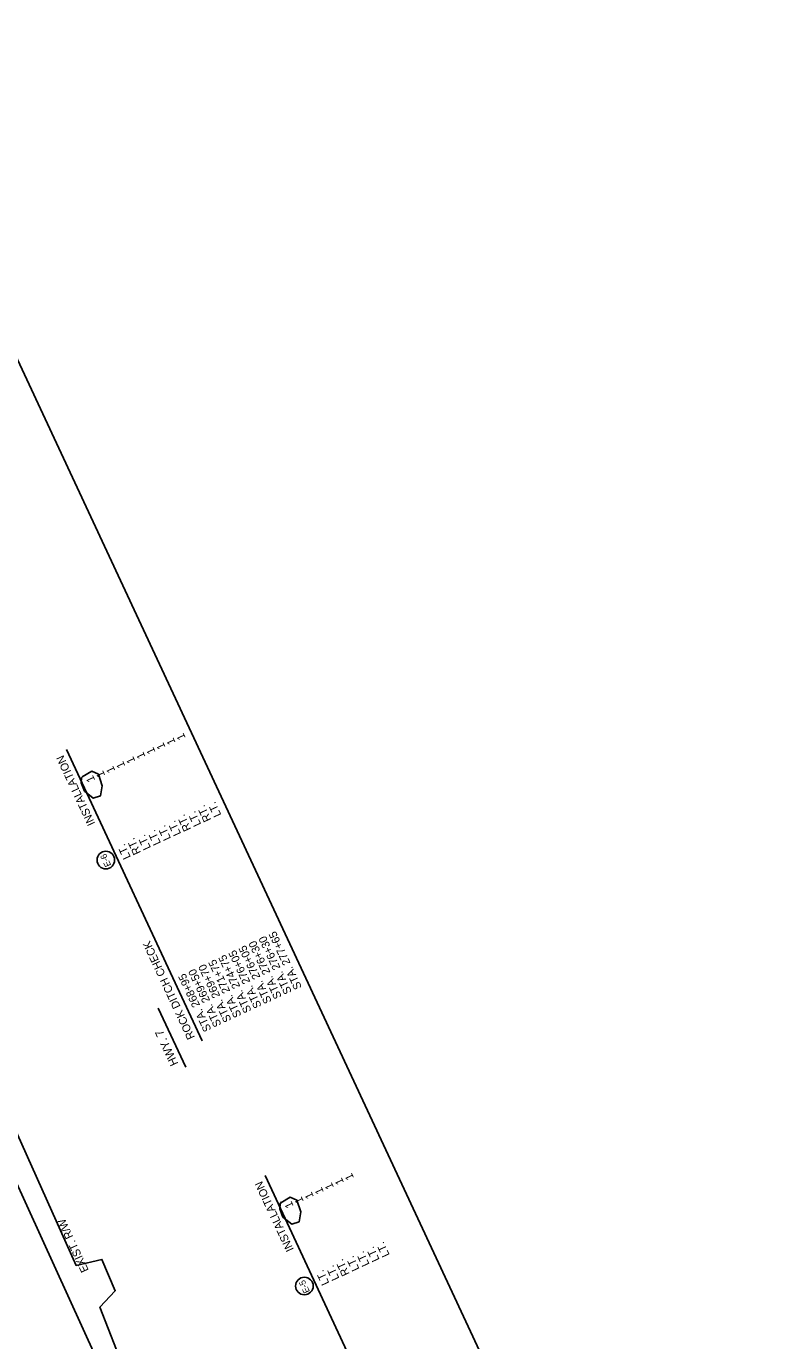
# Model space of a CAD drawing. Extents: x 964229 to 965790, y 1899262 to 1901149.
# Drawn here: x 965239 to 965790, y 1900163 to 1901149 of the extents above; entities that cross this region are included whole.
import ezdxf

# ---------------------------------------------------------------- set-up
doc = ezdxf.new("R2010")
doc.units = 0
for name, color, linetype in [('1', 7, 'Continuous'), ('44', 7, 'Continuous'), ('NO PLOT', 7, 'Continuous'), ('R_Draft', 7, 'Continuous'), ('S_TREE', 7, 'Continuous')]:
    doc.layers.add(name, color=color, linetype=linetype)

msp = doc.modelspace()

# ---------------------------------------------------------------- linework, layer by layer
at = {"layer": '1'}
for centre in [(965298.54, 1900523.47), (965447.48, 1900204.08)]:
    msp.add_circle(centre, 6.61, dxfattribs=at)
at = {"layer": '44'}
for p, q in [((965370.87, 1900387.83), (965269.02, 1900606.26)), ((965358.48, 1900368.05), (965337.83, 1900412.32)), ((965519.81, 1900068.44), (965417.95, 1900286.86))]:
    msp.add_line(p, q, dxfattribs=at)
at = {"layer": 'NO PLOT'}
msp.add_lwpolyline([(965789.77, 1899702.74), (965115.54, 1901148.63), (964643.21, 1900928.38), (964770.42, 1900655.58), (964831.6, 1900684.11), (965011.21, 1900298.93), (964950.03, 1900270.4), (965070.98, 1900011.03), (965126.95, 1900037.14), (965271.77, 1899726.58), (965215.79, 1899700.48), (965317.44, 1899482.49)], close=True, dxfattribs=at)
msp.add_lwpolyline([(965789.77, 1899702.74), (965115.54, 1901148.63), (964643.21, 1900928.38), (964770.42, 1900655.58), (964831.6, 1900684.11), (965011.21, 1900298.93), (964950.03, 1900270.4), (965070.98, 1900011.03), (965126.95, 1900037.14), (965271.77, 1899726.58), (965215.79, 1899700.48), (965317.44, 1899482.49)], close=True, dxfattribs=at)
msp.add_lwpolyline([(965789.77, 1899702.74), (965115.54, 1901148.63), (964643.21, 1900928.38), (964770.42, 1900655.58), (964831.6, 1900684.11), (965011.21, 1900298.93), (964950.03, 1900270.4), (965070.98, 1900011.03), (965126.95, 1900037.14), (965271.77, 1899726.58), (965215.79, 1899700.48), (965317.44, 1899482.49)], close=True, dxfattribs=at)
msp.add_lwpolyline([(965789.77, 1899702.74), (965115.54, 1901148.63), (964643.21, 1900928.38), (964770.42, 1900655.58), (964831.6, 1900684.11), (965011.21, 1900298.93), (964950.03, 1900270.4), (965070.98, 1900011.03), (965126.95, 1900037.14), (965271.77, 1899726.58), (965215.79, 1899700.48), (965317.44, 1899482.49)], close=True, dxfattribs=at)
for points in [[(965176.25, 1900402.21), (965291.71, 1900149.32)], [(965312.89, 1900140.18), (965294.07, 1900188.1), (965305.55, 1900200.5), (965295.63, 1900224.04), (965276.22, 1900219.57), (965209.45, 1900368.04)]]:
    msp.add_lwpolyline(points, dxfattribs=at)
at = {"layer": 'S_TREE'}
for points in [[(965280.79, 1900585.93), (965287.94, 1900590.06), (965292.98, 1900587.75), (965295.89, 1900579.15), (965294.61, 1900571.62), (965289.04, 1900569.86), (965282.47, 1900575.19), (965280.06, 1900581.45), (965280.35, 1900585.14), (965281.43, 1900586.46)], [(965429.73, 1900266.54), (965436.87, 1900270.66), (965441.92, 1900268.36), (965444.83, 1900259.76), (965443.55, 1900252.23), (965437.97, 1900250.47), (965431.4, 1900255.8), (965428.99, 1900262.06), (965429.28, 1900265.75), (965430.37, 1900267.07)]]:
    msp.add_lwpolyline(points, dxfattribs=at)

# ---------------------------------------------------------------- texts
at = {"layer": '1'}
for s, p in [('E-6 ', (965302.63, 1900519.64)), ('E-5 ', (965451.69, 1900199.98))]:
    msp.add_text(s, height=4.8, rotation=115, dxfattribs=at).set_placement(p)
at = {"layer": '44'}
for s, height, p in [('1', 6, (965350.96, 1900611.57)), ('1', 6, (965358.51, 1900615.1)), ('1', 6, (965328.34, 1900601.03)), ('1', 6, (965335.89, 1900604.55)), ('1', 6, (965343.41, 1900608.05)), ('INSTALLATION', 6, (965290.7, 1900550.87)), ('1', 6, (965305.72, 1900590.48)), ('1', 6, (965313.24, 1900593.99)), ('1', 6, (965320.79, 1900597.51)), ('1', 6, (965290.62, 1900583.44)), ('1', 6, (965298.17, 1900586.96)), ('RT.', 6, (965377.79, 1900553.65)), ('LT.', 6, (965385.28, 1900557.3)), ('LT.', 6, (965355.11, 1900543.23)), ('RT.', 6, (965362.72, 1900546.62)), ('LT.', 6, (965370.18, 1900550.26)), ('LT.', 6, (965340.01, 1900536.19)), ('LT.', 6, (965347.56, 1900539.71)), ('LT.', 6, (965317.39, 1900525.64)), ('RT.', 6, (965325, 1900529.03)), ('LT.', 6, (965332.49, 1900532.68)), ('STA. 276+30', 6, (965438.17, 1900424.5)), ('STA. 277+65', 6, (965445.72, 1900428.02)), ('ROCK DITCH CHECK', 6, (965365.44, 1900390.59)), ('STA. 276+05', 6, (965415.55, 1900413.95)), ('STA. 276+05', 6, (965423.11, 1900417.47)), ('STA. 276+30', 6, (965430.62, 1900420.98)), ('STA. 269+70', 6, (965392.94, 1900403.41)), ('STA. 271+75', 6, (965400.45, 1900406.91)), ('STA. 274+75', 6, (965408, 1900410.43)), ('STA. 268+95', 6, (965377.83, 1900396.36)), ('STA. 269+50', 6, (965385.39, 1900399.88)), ('HWY. 7', 6.25, (965353, 1900370.84)), ('1', 6, (965484.79, 1900285.14)), ('INSTALLATION', 6, (965439.64, 1900231.48)), ('1', 6, (965462.17, 1900274.59)), ('1', 6, (965469.72, 1900278.12)), ('1', 6, (965477.28, 1900281.64)), ('1', 6, (965439.56, 1900264.05)), ('1', 6, (965447.11, 1900267.57)), ('1', 6, (965454.66, 1900271.09)), ('LT.', 6, (965496.49, 1900220.32)), ('LT.', 6, (965504.04, 1900223.84)), ('LT.', 6, (965511.59, 1900227.36)), ('LT.', 6, (965473.87, 1900209.77)), ('RT.', 6, (965481.49, 1900213.17)), ('LT.', 6, (965488.94, 1900216.8)), ('LT.', 6, (965466.32, 1900206.25))]:
    msp.add_text(s, height=height, rotation=115, dxfattribs=at).set_placement(p)
at = {"layer": 'R_Draft'}
msp.add_text('EXIST. R/W', height=6, rotation=114.88908, dxfattribs=at).set_placement((965285.84, 1900215.93))

doc.saveas('drawing.dxf')
